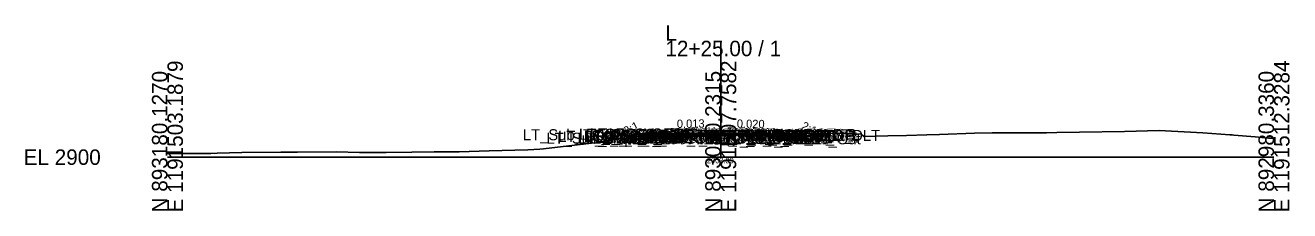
# Model space of a CAD drawing. Extents: x -26 to 203, y -10 to 7027.
# Drawn here: x -25.7 to 202.8, y 4490.3 to 4523.9 of the extents above; entities that cross this region are included whole.
import ezdxf

# ---------------------------------------------------------------- set-up
doc = ezdxf.new("R2010")
doc.units = 0
for name, color, linetype in [('Default', 7, 'Continuous'), ('Exist CMT Pavement', 7, 'Continuous'), ('Exist Cross Section Cell', 7, 'Continuous'), ('Exist XS Center Line Elevation Label', 7, 'Continuous'), ('Exist XS Ground Line', 7, 'Continuous'), ('Prop CMT Concrete Structures', 7, 'Continuous'), ('Prop CMT Pvmt Course 1', 7, 'Continuous'), ('Prop CMT Pvmt Course 2', 7, 'Continuous'), ('Prop CMT Pvmt Course 2 Wedge', 7, 'Continuous'), ('Prop CMT Pvmt Course 3', 7, 'Continuous'), ('Prop CMT Pvmt Course 3 Wedge', 7, 'Continuous'), ('Prop CMT Pvmt Surface', 7, 'Continuous'), ('Prop CMT Pvmt Surface Shoulder', 7, 'Continuous'), ('Prop CMT Pvmt Wedge Surface 3', 7, 'Continuous'), ('Prop CMT Shld Paved Course 1', 7, 'Continuous'), ('Prop CMT Shld Paved Course 2', 7, 'Continuous'), ('Prop CMT Shld Paved Course 3', 7, 'Continuous'), ('Prop CMT Slope Grass', 7, 'Continuous'), ('Prop CMT Subgrade Earthwork', 7, 'Continuous'), ('Scratch_Level_6', 7, 'Continuous')]:
    doc.layers.add(name, color=color, linetype=linetype)

msp = doc.modelspace()

# ---------------------------------------------------------------- linework, layer by layer
at = {"layer": 'Exist CMT Pavement'}
for points in [[(89, 4504.03), (85.34, 4503.98), (85.13, 4503.77)], [(85.13, 4503.77), (89, 4503.82)], [(89, 4503.82), (89, 4504.03)], [(89.33, 4503.45), (94.67, 4503.9)], [(100, 4503.89), (89.33, 4503.45)], [(94.67, 4503.9), (100, 4503.89)], [(100, 4503.89), (108.66, 4503.91)], [(104.33, 4503.89), (100, 4503.89)], [(108.66, 4503.91), (104.33, 4503.89)], [(111, 4503.96), (114.66, 4503.88), (114.87, 4503.67)], [(111, 4503.75), (111, 4503.96)], [(114.87, 4503.67), (111, 4503.75)]]:
    msp.add_lwpolyline(points, dxfattribs=at)
at = {"layer": 'Exist Cross Section Cell'}
for p, q in [((100, 4500), (100, 4521.06)), ((0, 4500), (100, 4500)), ((100, 4500), (200, 4500))]:
    msp.add_line(p, q, dxfattribs=at)
at = {"layer": 'Exist XS Center Line Elevation Label'}
for points in [[(100, 4504.18), (89.33, 4504.04)], [(100, 4504.18), (108.66, 4504)]]:
    msp.add_lwpolyline(points, dxfattribs=at)
at = {"layer": 'Exist XS Ground Line'}
for points in [[(100, 4504.26), (89.33, 4504.12)], [(100, 4504.26), (108.66, 4504.09)]]:
    msp.add_lwpolyline(points, dxfattribs=at)
at = {"layer": 'Prop CMT Concrete Structures'}
for points in [[(100, 4504.39), (89, 4504.24)], [(100, 4504.39), (111, 4504.16)]]:
    msp.add_lwpolyline(points, dxfattribs=at)
at = {"layer": 'Prop CMT Pvmt Course 1'}
for points in [[(100, 4504.39), (89, 4504.24)], [(100, 4504.18), (100, 4504.39)], [(100, 4504.39), (111, 4504.16)], [(100, 4504.18), (100, 4504.39)], [(89, 4504.24), (89, 4504.03)], [(89, 4504.03), (89.33, 4504.04)], [(89.33, 4504.04), (89, 4504.03)], [(89, 4504.03), (89, 4503.82)], [(89, 4503.82), (89.33, 4503.83)], [(89.33, 4504.12), (100, 4504.26)], [(89.33, 4504.04), (89.33, 4504.12)], [(89.33, 4503.83), (89.33, 4504.04)], [(100, 4504.26), (100, 4504.18), (100, 4504.18)], [(108.66, 4504.09), (100, 4504.26)], [(100, 4504.26), (100, 4504.18), (100, 4504.18)], [(108.66, 4504), (108.66, 4504.09)], [(111, 4503.96), (108.66, 4504)], [(108.66, 4503.8), (108.66, 4504)], [(108.66, 4504), (111, 4503.96)], [(111, 4503.75), (108.66, 4503.8)], [(111, 4504.16), (111, 4503.96)], [(111, 4503.96), (111, 4503.75)]]:
    msp.add_lwpolyline(points, dxfattribs=at)
at = {"layer": 'Prop CMT Pvmt Course 2'}
for points in [[(100, 4503.97), (89.33, 4503.83)], [(100, 4503.97), (108.66, 4503.8)]]:
    msp.add_lwpolyline(points, dxfattribs=at)
at = {"layer": 'Prop CMT Pvmt Course 3'}
for points in [[(89.33, 4503.83), (89, 4503.82)], [(89, 4503.82), (89, 4503.49)], [(89, 4503.49), (89.33, 4503.5)], [(89.33, 4503.5), (89.33, 4503.83)], [(108.66, 4503.8), (111, 4503.75)], [(108.66, 4503.46), (108.66, 4503.8)], [(111, 4503.42), (108.66, 4503.46)], [(111, 4503.75), (111, 4503.42)]]:
    msp.add_lwpolyline(points, dxfattribs=at)
at = {"layer": 'Prop CMT Pvmt Course 3 Wedge'}
for p, q in [((145.84, 4504.36), (149.09, 4504.4)), ((149.09, 4504.4), (158.86, 4504.43)), ((158.86, 4504.43), (160.75, 4504.45)), ((160.75, 4504.45), (164.82, 4504.52)), ((164.82, 4504.52), (172.95, 4504.67)), ((172.95, 4504.67), (179.25, 4504.83)), ((179.25, 4504.83), (187.16, 4504.38)), ((187.16, 4504.38), (192.02, 4504.05)), ((67.94, 4501.49), (76.65, 4502.52)), ((76.65, 4502.52), (77.74, 4502.58)), ((77.74, 4502.58), (78.55, 4502.81)), ((78.55, 4502.81), (82.13, 4503.39)), ((82.13, 4503.39), (83.83, 4503.46)), ((83.83, 4503.46), (88.5, 4503.44)), ((88.5, 4503.44), (89.4, 4503.45)), ((89.4, 4503.45), (90.85, 4503.64)), ((90.85, 4503.64), (91.09, 4503.87)), ((91.09, 4503.87), (94.67, 4503.9)), ((94.67, 4503.9), (99.42, 4503.89)), ((99.42, 4503.89), (100, 4503.89)), ((100, 4503.89), (104.38, 4503.89)), ((104.38, 4503.89), (108.66, 4503.91)), ((108.66, 4503.91), (110.01, 4503.4)), ((110.01, 4503.4), (111.16, 4503.06)), ((111.16, 4503.06), (112.61, 4503.51)), ((112.61, 4503.51), (114.58, 4503.82)), ((114.58, 4503.82), (119.47, 4504.35)), ((119.47, 4504.35), (122.46, 4504.26)), ((122.46, 4504.26), (125.39, 4504.17)), ((125.39, 4504.17), (125.85, 4503.75)), ((125.85, 4503.75), (130.21, 4503.84)), ((130.21, 4503.84), (133.55, 4503.92)), ((133.55, 4503.92), (137.27, 4504.04)), ((137.27, 4504.04), (139.55, 4504.12)), ((139.55, 4504.12), (145.84, 4504.36)), ((192.02, 4504.05), (192.43, 4504.01)), ((192.43, 4504.01), (192.77, 4503.99)), ((192.77, 4503.99), (196.61, 4503.66)), ((196.61, 4503.66), (199.01, 4503.46)), ((199.01, 4503.46), (200, 4503.43)), ((0, 4500.64), (4.32, 4500.67)), ((4.32, 4500.67), (7.85, 4500.69)), ((7.85, 4500.69), (8.98, 4500.72)), ((8.98, 4500.72), (13.43, 4500.87)), ((13.43, 4500.87), (20.49, 4500.88)), ((20.49, 4500.88), (23.49, 4500.91)), ((23.49, 4500.91), (30.53, 4500.98)), ((30.53, 4500.98), (34.72, 4500.84)), ((34.72, 4500.84), (39.51, 4500.86)), ((39.51, 4500.86), (44.17, 4500.91)), ((44.17, 4500.91), (48.23, 4500.95)), ((48.23, 4500.95), (52.09, 4500.94)), ((52.09, 4500.94), (52.73, 4500.95)), ((52.73, 4500.95), (58.15, 4501.12)), ((58.15, 4501.12), (65.15, 4501.34)), ((65.15, 4501.34), (67.3, 4501.46)), ((67.3, 4501.46), (67.94, 4501.49))]:
    msp.add_line(p, q, dxfattribs=at)
at = {"layer": 'Prop CMT Pvmt Surface'}
for points in [[(85.56, 4504.2), (85, 4504.15), (83.6, 4503.45)], [(114.44, 4504.1), (115, 4504.05), (115.31, 4503.9)]]:
    msp.add_lwpolyline(points, dxfattribs=at)
at = {"layer": 'Prop CMT Pvmt Surface Shoulder'}
for points in [[(89, 4504.24), (85.56, 4504.2)], [(111, 4504.16), (114.44, 4504.1)]]:
    msp.add_lwpolyline(points, dxfattribs=at)
at = {"layer": 'Prop CMT Shld Paved Course 1'}
for points in [[(89, 4504.24), (85.56, 4504.2), (85.34, 4503.98)], [(85.34, 4503.98), (89, 4504.03)], [(89, 4504.03), (89, 4504.24)], [(89, 4504.03), (89, 4504.24)], [(89.33, 4504.04), (89, 4504.03)], [(100, 4504.26), (89.33, 4504.12)], [(89.33, 4504.12), (89.33, 4504.04)], [(100, 4504.26), (108.66, 4504.09)], [(108.66, 4504.09), (108.66, 4504)], [(108.66, 4504), (111, 4503.96)], [(111, 4504.16), (114.44, 4504.1), (114.66, 4503.88)], [(111, 4503.96), (111, 4504.16)], [(111, 4503.96), (111, 4504.16)], [(114.66, 4503.88), (111, 4503.96)]]:
    msp.add_lwpolyline(points, dxfattribs=at)
at = {"layer": 'Prop CMT Shld Paved Course 2'}
for points in [[(89, 4504.03), (89, 4504.24)], [(100, 4504.18), (89, 4504.03)], [(100, 4504.18), (111, 4503.96)], [(111, 4503.96), (111, 4504.16)]]:
    msp.add_lwpolyline(points, dxfattribs=at)
at = {"layer": 'Prop CMT Shld Paved Course 3'}
for points in [[(89, 4503.82), (89, 4504.24)], [(100, 4503.97), (89, 4503.82)], [(100, 4503.97), (111, 4503.75)], [(111, 4503.75), (111, 4504.16)]]:
    msp.add_lwpolyline(points, dxfattribs=at)
at = {"layer": 'Prop CMT Slope Grass'}
for points in [[(89, 4503.82), (85.13, 4503.77), (84.63, 4503.77), (84.3, 4503.43)], [(84.3, 4503.43), (89, 4503.49)], [(89, 4503.49), (89, 4503.82)], [(111, 4503.75), (114.87, 4503.67), (115.37, 4503.66), (115.71, 4503.32)], [(111, 4503.42), (111, 4503.75)], [(115.71, 4503.32), (111, 4503.42)]]:
    msp.add_lwpolyline(points, dxfattribs=at)
at = {"layer": 'Prop CMT Subgrade Earthwork'}
for points in [[(84.3, 4503.43), (84.05, 4503.68)], [(89, 4503.49), (84.3, 4503.43)], [(89.33, 4503.5), (89, 4503.49)], [(89.33, 4503.5), (89.35, 4503.45)], [(108.66, 4503.46), (108.64, 4503.91)], [(108.66, 4503.46), (111, 4503.42)], [(111, 4503.42), (115.71, 4503.32)], [(115.71, 4503.32), (115.31, 4503.9)]]:
    msp.add_lwpolyline(points, dxfattribs=at)

# ---------------------------------------------------------------- texts
at = {"layer": 'Default'}
msp.add_text('-', height=0.0001, dxfattribs=at).set_placement((0, 4500))
at = {"layer": 'Exist Cross Section Cell'}
for s, p in [('L', (90, 4521.06)), ('12+25.00 / 1', (90, 4518.26)), ('EL 2900', (-26, 4498.6))]:
    msp.add_text(s, height=2.8, dxfattribs=at).set_placement(p)
for s, p in [('E 1191503.1879', (2.8, 4490)), ('E 1191507.7582', (102.8, 4490)), ('E 1191512.3284', (202.8, 4490)), ('N 893180.1270', (0, 4490)), ('N 893080.2315', (100, 4490)), ('N 892980.3360', (200, 4490))]:
    msp.add_text(s, height=2.8, rotation=90, dxfattribs=at).set_placement(p)
at = {"layer": 'Prop CMT Pvmt Course 2 Wedge'}
for s, p in [('LT_Sub_Trench_Out_DLT', (64.23, 4503.06)), ('LT_Sub_Trench_Out', (68.5, 4502.43)), ('LT_PS3_Shelf_Out', (70.62, 4502.77)), ('LT_Slope_Fill', (74.12, 4502.45)), ('LT_PV_Sub_Tie_Out', (74.29, 4502.45)), ('LT_GS_OS_CTL', (74.37, 4503.15)), ('LT_PS3_OEOP', (75.37, 4502.77)), ('LT_PS2_OEOP', (75.58, 4502.98)), ('LT_PS1_OEOP', (76.36, 4503.2)), ('LT_PV_OEEOP_EG', (76.88, 4502.45)), ('LT_Sub_OEEOP', (78.55, 4502.5)), ('LT_PV2_OEEOP', (78.64, 4503.04)), ('LT_PV3_OEEOP', (78.64, 4502.83)), ('LT_Sub_OEOT', (79.08, 4502.49)), ('LT_PV2_OEOT', (79.17, 4503.03)), ('LT_PV3_OEOT', (79.17, 4502.82)), ('LT_PV1_OEEOP', (79.21, 4503.12)), ('LT_PV1_OEOT', (79.74, 4503.24)), ('LT_PV_EG_TestPt', (81.08, 4502.9)), ('RT_PV_IEEOP_EG', (88.14, 4502.89)), ('LT_PV_IEEOP_EG', (88.19, 4502.89)), ('RT_PV2_IEEOP', (89.91, 4503.18)), ('RT_PV3_IEEOP', (89.91, 4502.97)), ('LT_PV2_IEEOP', (89.95, 4503.18)), ('LT_PV3_IEEOP', (89.95, 4502.97)), ('RT_PV1_IEEOP', (90.47, 4503.26)), ('LT_PV1_IEEOP', (90.52, 4503.26)), ('RT_PV_EG_TestPt', (90.69, 4502.89)), ('RT_PV_Sub_Tie_Out', (93.54, 4502.91)), ('PV2_PGL', (93.91, 4503.18)), ('PV1_PGL', (94.47, 4503.39)), ('RT_PV_OEEOP_EG', (96.16, 4502.91)), ('RT_Sub_Trench_Out_DLT', (96.85, 4502.94)), ('RT_Sub_OEEOP', (97.83, 4502.46)), ('RT_PV2_OEEOP', (97.92, 4503)), ('RT_PV3_OEEOP', (97.92, 4502.8)), ('RT_PV1_OEEOP', (98.49, 4503.09)), ('RT_Sub_Trench_Out', (99.87, 4502.32)), ('RT_Sub_OEOT', (101.03, 4502.42)), ('RT_PV2_OEOT', (101.13, 4502.96)), ('RT_PV3_OEOT', (101.13, 4502.75)), ('RT_PS3_Shelf_Out', (101.31, 4502.66)), ('RT_PV1_OEOT', (101.69, 4503.16)), ('RT_GS_OS_CTL', (104.32, 4503.05)), ('RT_PS2_OEOP', (104.85, 4502.88)), ('RT_PS3_OEOP', (105.06, 4502.67)), ('RT_PS1_OEOP', (105.2, 4503.1)), ('RT_Slope_Fill', (105.78, 4502.9))]:
    msp.add_text(s, height=2, dxfattribs=at).set_placement(p)
at = {"layer": 'Prop CMT Pvmt Surface Shoulder'}
for s, rotation, p in [('0.013', 0.752, (92.08, 4505.28)), ('0.020', 358.8542, (102.9, 4505.33))]:
    msp.add_text(s, height=1.5, rotation=rotation, dxfattribs=at).set_placement(p)
at = {"layer": 'Prop CMT Pvmt Wedge Surface 3'}
for rotation, p in [(26.5651, (82.9, 4503.94)), (333.4349, (114.43, 4505.18))]:
    msp.add_text('2:1', height=1.5, rotation=rotation, dxfattribs=at).set_placement(p)
at = {"layer": 'Scratch_Level_6'}
msp.add_text('2903.89', height=1, dxfattribs=at).set_placement((97.51, 4498.89))

doc.saveas('drawing.dxf')
